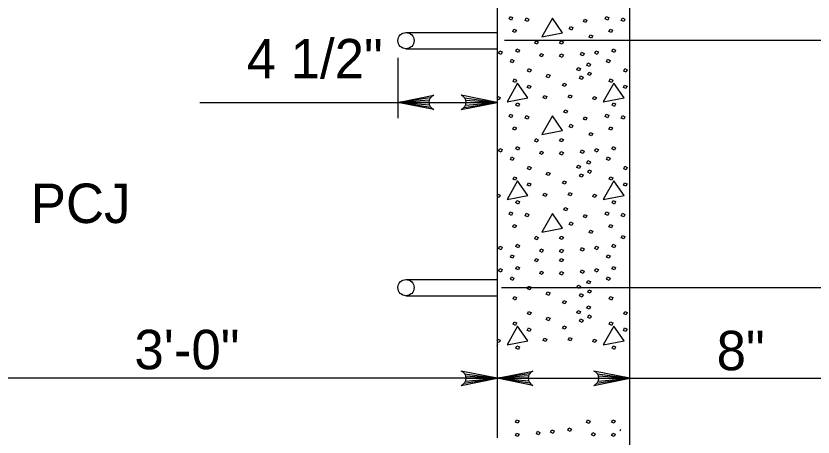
# Model space of a CAD drawing. Extents: x 0 to 34, y 0 to 22.
# Drawn here: x 9.818 to 12.969, y 3.328 to 4.994 of the extents above; entities that cross this region are included whole.
import ezdxf

# ---------------------------------------------------------------- set-up
doc = ezdxf.new("R2010")
doc.units = 0
doc.layers.add('Default', color=7, linetype='Continuous')

msp = doc.modelspace()

# ---------------------------------------------------------------- linework, layer by layer
at = {"layer": 'Default'}
for p, q in [((11.7202, 5.8753), (11.7202, 3.325)), ((12.2445, 2.1752), (12.2445, 5.8753)), ((11.3601, 4.9284), (11.7202, 4.9284)), ((11.7499, 4.8982), (13.5198, 4.8982)), ((11.3601, 4.8645), (11.7202, 4.8645)), ((11.3281, 4.8285), (11.3281, 4.5898)), ((11.4564, 4.6703), (11.3281, 4.6523)), ((11.592, 4.6703), (11.7202, 4.6523)), ((10.545, 4.6523), (11.7202, 4.6523)), ((11.452, 4.6614), (11.3281, 4.6523)), ((11.4507, 4.6523), (11.3281, 4.6523)), ((11.453, 4.6408), (11.3281, 4.6523)), ((11.4579, 4.6325), (11.3281, 4.6523)), ((11.5905, 4.6325), (11.7202, 4.6523)), ((11.5955, 4.6408), (11.7202, 4.6523)), ((11.5964, 4.6614), (11.7202, 4.6523)), ((11.5977, 4.6523), (11.7202, 4.6523)), ((11.3601, 3.9515), (11.7202, 3.9515)), ((11.7372, 3.9206), (13.5198, 3.9206)), ((11.3601, 3.8875), (11.7202, 3.8875)), ((11.7202, 3.561), (9.3457, 3.561)), ((11.5905, 3.5412), (11.7202, 3.561)), ((11.592, 3.579), (11.7202, 3.561)), ((11.5955, 3.5495), (11.7202, 3.561)), ((11.5964, 3.5701), (11.7202, 3.561)), ((11.5977, 3.561), (11.7202, 3.561)), ((11.8485, 3.579), (11.7202, 3.561)), ((11.8441, 3.5701), (11.7202, 3.561)), ((11.7202, 3.561), (13.0495, 3.561)), ((11.8428, 3.561), (11.7202, 3.561)), ((11.845, 3.5495), (11.7202, 3.561)), ((11.85, 3.5412), (11.7202, 3.561)), ((12.1148, 3.5412), (12.2445, 3.561)), ((12.1163, 3.579), (12.2445, 3.561)), ((12.1196, 3.5495), (12.2445, 3.561)), ((12.1206, 3.5701), (12.2445, 3.561)), ((12.122, 3.561), (12.2445, 3.561))]:
    msp.add_line(p, q, dxfattribs=at)
for points in [[(11.7717, 4.9918), (11.7817, 4.9878), (11.7777, 4.9778), (11.7677, 4.9825), (11.7717, 4.9918)], [(11.8356, 4.9865), (11.8456, 4.9818), (11.8416, 4.9725), (11.8316, 4.9765), (11.8356, 4.9865)], [(11.939, 4.9852), (11.8976, 4.9112), (11.9796, 4.9272), (11.939, 4.9852)], [(12.0655, 4.9818), (12.0755, 4.9772), (12.0715, 4.9678), (12.0615, 4.9725), (12.0655, 4.9818)], [(12.1515, 4.9918), (12.1615, 4.9878), (12.1575, 4.9778), (12.1475, 4.9825), (12.1515, 4.9918)], [(12.2155, 4.9865), (12.2255, 4.9818), (12.2215, 4.9725), (12.2115, 4.9765), (12.2155, 4.9865)], [(12.0102, 4.9525), (12.0202, 4.9478), (12.0155, 4.9385), (12.0055, 4.9425), (12.0102, 4.9525)], [(11.787, 4.9418), (11.797, 4.9378), (11.7924, 4.9285), (11.7824, 4.9325), (11.787, 4.9418)], [(12.0882, 4.9198), (12.0982, 4.9158), (12.0942, 4.9058), (12.0842, 4.9105), (12.0882, 4.9198)], [(12.1669, 4.9418), (12.1769, 4.9378), (12.1722, 4.9285), (12.1622, 4.9325), (12.1669, 4.9418)], [(11.873, 4.8958), (11.883, 4.8912), (11.879, 4.8819), (11.869, 4.8859), (11.873, 4.8958)], [(11.9723, 4.8958), (11.9823, 4.8918), (11.9776, 4.8826), (11.9676, 4.8865), (11.9723, 4.8958)], [(11.731, 4.8559), (11.741, 4.8519), (11.7364, 4.8419), (11.7264, 4.8466), (11.731, 4.8559)], [(11.799, 4.8639), (11.809, 4.8592), (11.8044, 4.8499), (11.7944, 4.8546), (11.799, 4.8639)], [(12.1109, 4.8559), (12.1209, 4.8519), (12.1162, 4.8419), (12.1062, 4.8466), (12.1109, 4.8559)], [(12.1788, 4.8639), (12.1888, 4.8592), (12.1841, 4.8499), (12.1742, 4.8546), (12.1788, 4.8639)], [(11.777, 4.8226), (11.787, 4.8179), (11.783, 4.8086), (11.773, 4.8132), (11.777, 4.8226)], [(11.893, 4.8459), (11.903, 4.8412), (11.899, 4.8319), (11.889, 4.8366), (11.893, 4.8459)], [(11.9723, 4.8439), (11.9823, 4.8399), (11.9776, 4.8299), (11.9676, 4.8346), (11.9723, 4.8439)], [(12.0542, 4.8506), (12.0642, 4.8459), (12.0602, 4.8366), (12.0502, 4.8406), (12.0542, 4.8506)], [(12.1569, 4.8226), (12.1669, 4.8179), (12.1629, 4.8086), (12.1529, 4.8132), (12.1569, 4.8226)], [(12.0395, 4.7899), (12.0495, 4.7859), (12.0455, 4.7766), (12.0355, 4.7806), (12.0395, 4.7899)], [(12.0795, 4.8086), (12.0895, 4.8039), (12.0855, 4.7946), (12.0755, 4.7986), (12.0795, 4.8086)], [(11.845, 4.7859), (11.855, 4.7812), (11.851, 4.7719), (11.841, 4.7759), (11.845, 4.7859)], [(11.9196, 4.7632), (11.9296, 4.7592), (11.925, 4.7492), (11.915, 4.7539), (11.9196, 4.7632)], [(12.0829, 4.7719), (12.0929, 4.7672), (12.0889, 4.7579), (12.0789, 4.7626), (12.0829, 4.7719)], [(12.2248, 4.7859), (12.2348, 4.7812), (12.2308, 4.7719), (12.2208, 4.7759), (12.2248, 4.7859)], [(11.8017, 4.728), (11.7604, 4.654), (11.8423, 4.67), (11.8017, 4.728)], [(11.7877, 4.7447), (11.7977, 4.7407), (11.7937, 4.7307), (11.7837, 4.7353), (11.7877, 4.7447)], [(11.9836, 4.7287), (11.9936, 4.7247), (11.9896, 4.7153), (11.9796, 4.7193), (11.9836, 4.7287)], [(12.0502, 4.7566), (12.0602, 4.7519), (12.0562, 4.7427), (12.0462, 4.7473), (12.0502, 4.7566)], [(12.1815, 4.728), (12.1402, 4.654), (12.2221, 4.67), (12.1815, 4.728)], [(12.1675, 4.7447), (12.1775, 4.7407), (12.1735, 4.7307), (12.1635, 4.7353), (12.1675, 4.7447)], [(11.8443, 4.7207), (11.8543, 4.716), (11.8496, 4.7067), (11.8396, 4.7107), (11.8443, 4.7207)], [(12.2241, 4.7207), (12.2341, 4.716), (12.2295, 4.7067), (12.2195, 4.7107), (12.2241, 4.7207)], [(11.4698, 4.6241), (11.3281, 4.6523), (11.4698, 4.6807)], [(11.5786, 4.6241), (11.7202, 4.6523), (11.5786, 4.6807)], [(11.723, 4.676), (11.733, 4.672), (11.7284, 4.6627), (11.7202, 4.6659)], [(11.7202, 4.6704), (11.723, 4.676)], [(11.907, 4.68), (11.917, 4.676), (11.913, 4.6667), (11.903, 4.6707), (11.907, 4.68)], [(12.0062, 4.6827), (12.0162, 4.6787), (12.0115, 4.6693), (12.0016, 4.6733), (12.0062, 4.6827)], [(12.1029, 4.676), (12.1129, 4.672), (12.1082, 4.6627), (12.0982, 4.6667), (12.1029, 4.676)], [(11.799, 4.65), (11.809, 4.646), (11.805, 4.636), (11.795, 4.6407), (11.799, 4.65)], [(12.1788, 4.65), (12.1888, 4.646), (12.1848, 4.636), (12.1748, 4.6407), (12.1788, 4.65)], [(11.7717, 4.6053), (11.7817, 4.6013), (11.7777, 4.5914), (11.7677, 4.5961), (11.7717, 4.6053)], [(11.9883, 4.6233), (11.9983, 4.6193), (11.9943, 4.61), (11.9843, 4.614), (11.9883, 4.6233)], [(12.1515, 4.6053), (12.1615, 4.6013), (12.1575, 4.5914), (12.1475, 4.5961), (12.1515, 4.6053)], [(11.8356, 4.6001), (11.8456, 4.5954), (11.8416, 4.5861), (11.8316, 4.5901), (11.8356, 4.6001)], [(11.939, 4.5987), (11.8976, 4.5247), (11.9796, 4.5407), (11.939, 4.5987)], [(12.0655, 4.5954), (12.0755, 4.5907), (12.0715, 4.5814), (12.0615, 4.5861), (12.0655, 4.5954)], [(12.2155, 4.6001), (12.2255, 4.5954), (12.2215, 4.5861), (12.2115, 4.5901), (12.2155, 4.6001)], [(11.787, 4.5554), (11.797, 4.5514), (11.7924, 4.5421), (11.7824, 4.5461), (11.787, 4.5554)], [(12.0102, 4.5661), (12.0202, 4.5614), (12.0155, 4.5521), (12.0055, 4.5561), (12.0102, 4.5661)], [(12.1669, 4.5554), (12.1769, 4.5514), (12.1722, 4.5421), (12.1622, 4.5461), (12.1669, 4.5554)], [(11.873, 4.5094), (11.883, 4.5047), (11.879, 4.4954), (11.869, 4.4994), (11.873, 4.5094)], [(11.9723, 4.5094), (11.9823, 4.5054), (11.9776, 4.4961), (11.9676, 4.5001), (11.9723, 4.5094)], [(12.0882, 4.5334), (12.0982, 4.5294), (12.0942, 4.5194), (12.0842, 4.5241), (12.0882, 4.5334)], [(11.799, 4.4774), (11.809, 4.4727), (11.8044, 4.4634), (11.7944, 4.4681), (11.799, 4.4774)], [(12.1788, 4.4774), (12.1888, 4.4727), (12.1841, 4.4634), (12.1742, 4.4681), (12.1788, 4.4774)], [(11.731, 4.4694), (11.741, 4.4654), (11.7364, 4.4555), (11.7264, 4.4601), (11.731, 4.4694)], [(11.893, 4.4595), (11.903, 4.4548), (11.899, 4.4455), (11.889, 4.4502), (11.893, 4.4595)], [(11.9723, 4.4575), (11.9823, 4.4535), (11.9776, 4.4435), (11.9676, 4.4482), (11.9723, 4.4575)], [(12.0542, 4.4641), (12.0642, 4.4595), (12.0602, 4.4502), (12.0502, 4.4542), (12.0542, 4.4641)], [(12.1109, 4.4694), (12.1209, 4.4654), (12.1162, 4.4555), (12.1062, 4.4601), (12.1109, 4.4694)], [(11.777, 4.4362), (11.787, 4.4315), (11.783, 4.4222), (11.773, 4.4268), (11.777, 4.4362)], [(12.0795, 4.4222), (12.0895, 4.4175), (12.0855, 4.4082), (12.0755, 4.4122), (12.0795, 4.4222)], [(12.1569, 4.4362), (12.1669, 4.4315), (12.1629, 4.4222), (12.1529, 4.4268), (12.1569, 4.4362)], [(11.845, 4.3995), (11.855, 4.3948), (11.851, 4.3855), (11.841, 4.3895), (11.845, 4.3995)], [(12.0395, 4.4035), (12.0495, 4.3995), (12.0455, 4.3902), (12.0355, 4.3942), (12.0395, 4.4035)], [(12.0829, 4.3855), (12.0929, 4.3808), (12.0889, 4.3715), (12.0789, 4.3762), (12.0829, 4.3855)], [(12.2248, 4.3995), (12.2348, 4.3948), (12.2308, 4.3855), (12.2208, 4.3895), (12.2248, 4.3995)], [(11.7877, 4.3582), (11.7977, 4.3542), (11.7937, 4.3442), (11.7837, 4.3488), (11.7877, 4.3582)], [(11.9196, 4.3768), (11.9296, 4.3728), (11.925, 4.3628), (11.915, 4.3675), (11.9196, 4.3768)], [(12.0502, 4.3702), (12.0602, 4.3655), (12.0562, 4.3562), (12.0462, 4.3608), (12.0502, 4.3702)], [(12.1675, 4.3582), (12.1775, 4.3542), (12.1735, 4.3442), (12.1635, 4.3488), (12.1675, 4.3582)], [(11.8017, 4.3415), (11.7604, 4.2676), (11.8423, 4.2836), (11.8017, 4.3415)], [(11.8443, 4.3342), (11.8543, 4.3295), (11.8496, 4.3202), (11.8396, 4.3242), (11.8443, 4.3342)], [(11.9836, 4.3422), (11.9936, 4.3382), (11.9896, 4.3288), (11.9796, 4.3328), (11.9836, 4.3422)], [(12.1815, 4.3415), (12.1402, 4.2676), (12.2221, 4.2836), (12.1815, 4.3415)], [(12.2241, 4.3342), (12.2341, 4.3295), (12.2295, 4.3202), (12.2195, 4.3242), (12.2241, 4.3342)], [(11.723, 4.2896), (11.733, 4.2856), (11.7284, 4.2762), (11.7202, 4.2795)], [(11.7202, 4.284), (11.723, 4.2896)], [(11.907, 4.2936), (11.917, 4.2896), (11.913, 4.2802), (11.903, 4.2842), (11.907, 4.2936)], [(12.0062, 4.2962), (12.0162, 4.2922), (12.0115, 4.2829), (12.0016, 4.2869), (12.0062, 4.2962)], [(12.1029, 4.2896), (12.1129, 4.2856), (12.1082, 4.2762), (12.0982, 4.2802), (12.1029, 4.2896)], [(11.799, 4.2636), (11.809, 4.2596), (11.805, 4.2496), (11.795, 4.2542), (11.799, 4.2636)], [(12.1788, 4.2636), (12.1888, 4.2596), (12.1848, 4.2496), (12.1748, 4.2542), (12.1788, 4.2636)], [(11.9883, 4.2369), (11.9983, 4.2329), (11.9943, 4.2236), (11.9843, 4.2276), (11.9883, 4.2369)], [(11.7717, 4.2189), (11.7817, 4.2149), (11.7777, 4.2049), (11.7677, 4.2096), (11.7717, 4.2189)], [(11.8356, 4.2136), (11.8456, 4.2089), (11.8416, 4.1996), (11.8316, 4.2036), (11.8356, 4.2136)], [(11.939, 4.2122), (11.8976, 4.1383), (11.9796, 4.1543), (11.939, 4.2122)], [(12.0655, 4.2089), (12.0755, 4.2042), (12.0715, 4.1949), (12.0615, 4.1996), (12.0655, 4.2089)], [(12.1515, 4.2189), (12.1615, 4.2149), (12.1575, 4.2049), (12.1475, 4.2096), (12.1515, 4.2189)], [(12.2155, 4.2136), (12.2255, 4.2089), (12.2215, 4.1996), (12.2115, 4.2036), (12.2155, 4.2136)], [(11.787, 4.169), (11.797, 4.165), (11.7924, 4.1557), (11.7824, 4.1597), (11.787, 4.169)], [(12.0102, 4.1796), (12.0202, 4.1749), (12.0155, 4.1656), (12.0055, 4.1697), (12.0102, 4.1796)], [(12.1669, 4.169), (12.1769, 4.165), (12.1722, 4.1557), (12.1622, 4.1597), (12.1669, 4.169)], [(12.0882, 4.147), (12.0982, 4.143), (12.0942, 4.133), (12.0842, 4.1377), (12.0882, 4.147)], [(11.873, 4.123), (11.883, 4.1183), (11.879, 4.109), (11.869, 4.113), (11.873, 4.123)], [(11.9723, 4.123), (11.9823, 4.119), (11.9776, 4.1097), (11.9676, 4.1137), (11.9723, 4.123)], [(12.2155, 4.1258), (12.2255, 4.1212), (12.2215, 4.1119), (12.2115, 4.1159), (12.2155, 4.1258)], [(11.731, 4.083), (11.741, 4.079), (11.7364, 4.069), (11.7264, 4.0737), (11.731, 4.083)], [(11.799, 4.091), (11.809, 4.0863), (11.8044, 4.077), (11.7944, 4.0817), (11.799, 4.091)], [(11.893, 4.073), (11.903, 4.0683), (11.899, 4.059), (11.889, 4.0637), (11.893, 4.073)], [(11.9723, 4.071), (11.9823, 4.067), (11.9776, 4.057), (11.9676, 4.0617), (11.9723, 4.071)], [(12.0542, 4.0777), (12.0642, 4.073), (12.0602, 4.0637), (12.0502, 4.0677), (12.0542, 4.0777)], [(12.1109, 4.083), (12.1209, 4.079), (12.1162, 4.069), (12.1062, 4.0737), (12.1109, 4.083)], [(12.1788, 4.091), (12.1888, 4.0863), (12.1841, 4.077), (12.1742, 4.0817), (12.1788, 4.091)], [(11.777, 4.0497), (11.787, 4.045), (11.783, 4.0357), (11.773, 4.0403), (11.777, 4.0497)], [(11.873, 4.0352), (11.883, 4.0306), (11.879, 4.0212), (11.869, 4.0252), (11.873, 4.0352)], [(11.9723, 4.0352), (11.9823, 4.0312), (11.9776, 4.0219), (11.9676, 4.0259), (11.9723, 4.0352)], [(12.1569, 4.0497), (12.1669, 4.045), (12.1629, 4.0357), (12.1529, 4.0403), (12.1569, 4.0497)], [(11.799, 4.0032), (11.809, 3.9986), (11.8044, 3.9892), (11.7944, 3.9939), (11.799, 4.0032)], [(12.1788, 4.0032), (12.1888, 3.9986), (12.1841, 3.9892), (12.1742, 3.9939), (12.1788, 4.0032)], [(11.731, 3.9952), (11.741, 3.9912), (11.7364, 3.9812), (11.7264, 3.9859), (11.731, 3.9952)], [(11.893, 3.9852), (11.903, 3.9806), (11.899, 3.9713), (11.889, 3.9759), (11.893, 3.9852)], [(11.9723, 3.9832), (11.9823, 3.9793), (11.9776, 3.9693), (11.9676, 3.974), (11.9723, 3.9832)], [(12.0542, 3.9899), (12.0642, 3.9852), (12.0602, 3.9759), (12.0502, 3.98), (12.0542, 3.9899)], [(12.1109, 3.9952), (12.1209, 3.9912), (12.1162, 3.9812), (12.1062, 3.9859), (12.1109, 3.9952)], [(11.777, 3.962), (11.787, 3.9573), (11.783, 3.948), (11.773, 3.9527), (11.777, 3.962)], [(12.0795, 3.948), (12.0895, 3.9433), (12.0855, 3.934), (12.0755, 3.938), (12.0795, 3.948)], [(12.1569, 3.962), (12.1669, 3.9573), (12.1629, 3.948), (12.1529, 3.9527), (12.1569, 3.962)], [(11.845, 3.9253), (11.855, 3.9207), (11.851, 3.9113), (11.841, 3.9153), (11.845, 3.9253)], [(12.0395, 3.9293), (12.0495, 3.9253), (12.0455, 3.916), (12.0355, 3.92), (12.0395, 3.9293)], [(12.0829, 3.9113), (12.0929, 3.9067), (12.0889, 3.8973), (12.0789, 3.902), (12.0829, 3.9113)], [(11.7877, 3.884), (11.7977, 3.88), (11.7937, 3.87), (11.7837, 3.8747), (11.7877, 3.884)], [(11.9196, 3.9027), (11.9296, 3.8987), (11.925, 3.8887), (11.915, 3.8933), (11.9196, 3.9027)], [(12.0502, 3.896), (12.0602, 3.8913), (12.0562, 3.882), (12.0462, 3.8867), (12.0502, 3.896)], [(12.1675, 3.884), (12.1775, 3.88), (12.1735, 3.87), (12.1635, 3.8747), (12.1675, 3.884)], [(11.9836, 3.868), (11.9936, 3.864), (11.9896, 3.8547), (11.9796, 3.8587), (11.9836, 3.868)], [(12.0795, 3.8479), (12.0895, 3.8432), (12.0855, 3.8339), (12.0755, 3.8379), (12.0795, 3.8479)], [(11.845, 3.8252), (11.855, 3.8206), (11.851, 3.8112), (11.841, 3.8152), (11.845, 3.8252)], [(12.0395, 3.8292), (12.0495, 3.8252), (12.0455, 3.8159), (12.0355, 3.8199), (12.0395, 3.8292)], [(12.2248, 3.8252), (12.2348, 3.8206), (12.2308, 3.8112), (12.2208, 3.8152), (12.2248, 3.8252)], [(11.7877, 3.784), (11.7977, 3.78), (11.7937, 3.77), (11.7837, 3.7747), (11.7877, 3.784)], [(11.9196, 3.8026), (11.9296, 3.7987), (11.925, 3.7887), (11.915, 3.7933), (11.9196, 3.8026)], [(12.0502, 3.796), (12.0602, 3.7913), (12.0562, 3.782), (12.0462, 3.7867), (12.0502, 3.796)], [(12.0829, 3.8112), (12.0929, 3.8066), (12.0889, 3.7973), (12.0789, 3.8019), (12.0829, 3.8112)], [(12.1675, 3.784), (12.1775, 3.78), (12.1735, 3.77), (12.1635, 3.7747), (12.1675, 3.784)], [(11.8017, 3.7673), (11.7604, 3.6933), (11.8423, 3.7093), (11.8017, 3.7673)], [(11.8443, 3.76), (11.8543, 3.7553), (11.8496, 3.746), (11.8396, 3.75), (11.8443, 3.76)], [(11.9836, 3.768), (11.9936, 3.764), (11.9896, 3.7547), (11.9796, 3.7587), (11.9836, 3.768)], [(12.1815, 3.7673), (12.1402, 3.6933), (12.2221, 3.7093), (12.1815, 3.7673)], [(12.2241, 3.76), (12.2341, 3.7553), (12.2295, 3.746), (12.2195, 3.75), (12.2241, 3.76)], [(11.907, 3.7193), (11.917, 3.7153), (11.913, 3.706), (11.903, 3.71), (11.907, 3.7193)], [(12.0062, 3.722), (12.0162, 3.718), (12.0115, 3.7087), (12.0016, 3.7127), (12.0062, 3.722)], [(11.723, 3.7153), (11.733, 3.7113), (11.7284, 3.702), (11.7202, 3.7052)], [(11.7202, 3.7097), (11.723, 3.7153)], [(11.7202, 3.6911), (11.723, 3.6967)], [(11.799, 3.6893), (11.809, 3.6853), (11.805, 3.6753), (11.795, 3.68), (11.799, 3.6893)], [(12.1029, 3.7153), (12.1129, 3.7113), (12.1082, 3.702), (12.0982, 3.706), (12.1029, 3.7153)], [(12.1788, 3.6893), (12.1888, 3.6853), (12.1848, 3.6753), (12.1748, 3.68), (12.1788, 3.6893)], [(11.5786, 3.5327), (11.7202, 3.561), (11.5786, 3.5893)], [(11.8619, 3.5327), (11.7202, 3.561), (11.8619, 3.5893)], [(12.1029, 3.5327), (12.2445, 3.561), (12.1029, 3.5893)], [(11.7977, 3.3963), (11.8077, 3.3923), (11.803, 3.383), (11.793, 3.387), (11.7977, 3.3963)], [(12.0782, 3.3963), (12.0882, 3.3917), (12.0842, 3.3823), (12.0742, 3.3863), (12.0782, 3.3963)], [(12.1775, 3.3963), (12.1875, 3.3923), (12.1829, 3.383), (12.1729, 3.387), (12.1775, 3.3963)], [(11.7977, 3.3444), (11.8077, 3.3404), (11.803, 3.3304), (11.793, 3.3351), (11.7977, 3.3444)], [(11.8796, 3.3511), (11.8896, 3.3464), (11.8856, 3.3371), (11.8756, 3.3411), (11.8796, 3.3511)], [(11.9363, 3.3564), (11.9463, 3.3524), (11.9416, 3.3424), (11.9316, 3.3471), (11.9363, 3.3564)], [(12.0043, 3.3643), (12.0142, 3.3597), (12.0096, 3.3504), (11.9996, 3.3551), (12.0043, 3.3643)], [(12.0982, 3.3464), (12.1082, 3.3417), (12.1042, 3.3324), (12.0942, 3.3371), (12.0982, 3.3464)], [(12.1775, 3.3444), (12.1875, 3.3404), (12.1829, 3.3304), (12.1729, 3.3351), (12.1775, 3.3444)], [(12.2097, 3.3527), (12.2068, 3.3538), (12.2097, 3.3595)]]:
    msp.add_lwpolyline(points, dxfattribs=at)
for centre, start, end in [((11.4812, 4.6524), 112.0878, 247.9139), ((11.5672, 4.6524), 292.0861, 67.9122), ((11.5672, 3.561), 292.0861, 67.9122), ((11.8733, 3.561), 112.0878, 247.9139), ((12.0914, 3.561), 292.0861, 67.9122)]:
    msp.add_arc(centre, 0.0306, start, end, dxfattribs=at)
for centre in [(11.3602, 4.8965), (11.3602, 3.9195)]:
    msp.add_ellipse(centre, major_axis=(0.032, 0), ratio=0.999895, dxfattribs=at)

# ---------------------------------------------------------------- texts
for s, p in [('4 1/2"', (10.7304, 4.7471)), ('PCJ', (9.877, 4.1749)), ('3\'-0"', (10.2868, 3.5966)), ('8"', (12.5882, 3.5927))]:
    msp.add_text(s, height=0.156, dxfattribs=at).set_placement(p)

doc.saveas('drawing.dxf')
